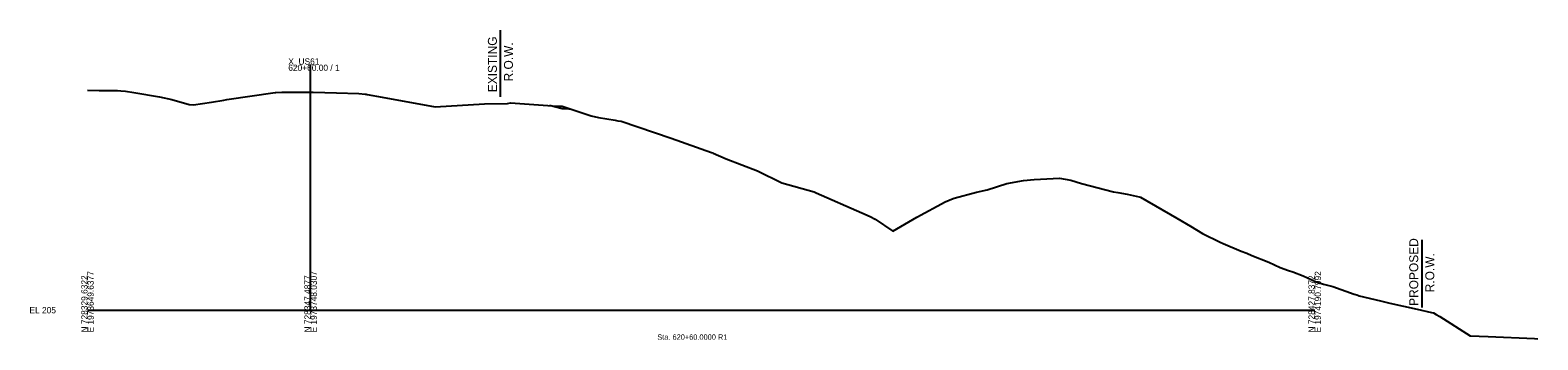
# Model space of a CAD drawing. Extents: x -26 to 1629, y -25 to 9635.
# Drawn here: x -26 to 650, y 1487 to 1625 of the extents above; entities that cross this region are included whole.
import ezdxf

# ---------------------------------------------------------------- set-up
doc = ezdxf.new("R2010")
doc.units = 0
for name, color, linetype in [('Draft_XS_Grid', 7, 'Continuous'), ('Draft_XS_Text', 7, 'Continuous'), ('DTM_X_GROUND', 7, 'Continuous'), ('XS_CELL', 7, 'Continuous'), ('XS_P_GROUND', 7, 'Continuous'), ('XS_P_ROW', 7, 'Continuous'), ('XS_X_ROW', 7, 'Continuous')]:
    doc.layers.add(name, color=color, linetype=linetype)

msp = doc.modelspace()

# ---------------------------------------------------------------- linework, layer by layer
at = {"layer": 'DTM_X_GROUND'}
msp.add_lwpolyline([(0, 1598.55), (5.26, 1598.48), (13.43, 1598.36), (14.97, 1598.25), (17.1, 1598.1), (20.71, 1597.57), (32.23, 1595.59), (37.8, 1594.33), (45.55, 1592.11), (47.57, 1592.04), (55.59, 1593.22), (61.06, 1594.14), (62.42, 1594.35), (84.15, 1597.45), (84.34, 1597.48), (84.48, 1597.49), (87.16, 1597.65), (94.94, 1597.67), (101.09, 1597.69), (111.61, 1597.33), (121.66, 1597), (124.38, 1596.78), (124.83, 1596.74), (125.4, 1596.65), (132.11, 1595.44), (155.87, 1591.1), (177.97, 1592.46), (188.31, 1592.66), (189.65, 1592.95), (208.37, 1591.53), (209.54, 1591.41), (209.82, 1591.37), (212.79, 1591.37), (220.86, 1588.66), (225.67, 1587), (229.02, 1586.29), (236.45, 1585.1), (237.63, 1584.83), (239.21, 1584.68), (261.6, 1577.1), (261.62, 1577.09), (261.62, 1577.09), (261.63, 1577.09), (279.61, 1570.66), (280.19, 1570.47), (280.36, 1570.41), (286.24, 1567.82), (300.22, 1562.41), (311.17, 1557.04), (325.62, 1552.95), (326.01, 1552.82), (326.22, 1552.74), (326.62, 1552.61), (346.99, 1543.61), (350.72, 1541.9), (353.04, 1540.83), (360.96, 1535.47), (371.74, 1541.68), (384.35, 1548.54), (387.99, 1550.02), (388.42, 1550.2), (398.49, 1552.87), (403.27, 1553.94), (411.95, 1556.79), (419.48, 1558.15), (424.27, 1558.6), (429.89, 1558.84), (435.65, 1559.08), (440.7, 1558.27), (445.44, 1556.8), (459.88, 1553.08), (461.83, 1552.67), (466.01, 1552.02), (471.31, 1550.77), (471.89, 1550.61), (488.17, 1541.2), (494.33, 1537.57), (499.64, 1534.37), (507.6, 1530.51), (508.98, 1529.93), (517.05, 1526.42), (519.6, 1525.53), (521.76, 1524.52), (529.47, 1521.57), (534.48, 1519.05), (538.28, 1517.73), (540.16, 1517.25), (544.76, 1515.36), (550.59, 1512.76), (553.88, 1511.7), (558.1, 1510.64), (567.74, 1507.19), (568.92, 1506.81), (569.56, 1506.6), (569.92, 1506.5), (579.42, 1504.25), (583.67, 1503.09), (595.99, 1500.38), (602.36, 1499), (603.22, 1498.85), (604.49, 1498.13), (606.03, 1497.16), (619.66, 1488.54), (627.75, 1488.16), (648.45, 1487.32), (650, 1487.23)], dxfattribs=at)
at = {"layer": 'XS_CELL'}
for p, q in [((100, 1500), (100, 1610)), ((0, 1500), (100, 1500)), ((100, 1500), (550, 1500))]:
    msp.add_line(p, q, dxfattribs=at)
at = {"layer": 'XS_P_GROUND'}
msp.add_line((212.79, 1590.25), (207.09, 1591.63), dxfattribs=at)
msp.add_lwpolyline([(216.96, 1589.97), (216.84, 1589.97), (216.84, 1589.97), (215.68, 1590.05), (215.67, 1590.05), (214.53, 1590.13), (214.49, 1590.13), (213.37, 1590.21), (213.35, 1590.21), (212.79, 1590.25)], dxfattribs=at)
at = {"layer": 'XS_P_ROW'}
msp.add_line((598, 1531.55), (598, 1501.23), dxfattribs=at)
at = {"layer": 'XS_X_ROW'}
msp.add_line((185, 1625.44), (185, 1595.54), dxfattribs=at)

# ---------------------------------------------------------------- texts
at = {"layer": 'Draft_XS_Grid'}
msp.add_text('-', height=0.0001, dxfattribs=at).set_placement((0, 1500))
at = {"layer": 'Draft_XS_Text'}
msp.add_text('Sta. 620+60.0000 R1', height=2.4, dxfattribs=at).set_placement((255.37, 1486.75))
at = {"layer": 'XS_CELL'}
for s, p in [('X_US61', (90, 1610)), ('620+60.00 / 1', (90, 1607.2)), ('EL 205', (-26, 1498.6))]:
    msp.add_text(s, height=2.8, dxfattribs=at).set_placement(p)
for s, p in [('N 728329.6322', (0, 1490)), ('E 1973649.6377', (2.8, 1490)), ('N 728347.4877', (100, 1490)), ('E 1973748.0307', (102.8, 1490)), ('N 728427.8372', (550, 1490)), ('E 1974190.7992', (552.8, 1490))]:
    msp.add_text(s, height=2.8, rotation=90, dxfattribs=at).set_placement(p)
at = {"layer": 'XS_P_ROW'}
for s, p in [('PROPOSED', (596.37, 1501.93)), ('R.O.W.', (603.57, 1508.01))]:
    msp.add_text(s, height=4, rotation=90, dxfattribs=at).set_placement(p)
at = {"layer": 'XS_X_ROW'}
for s, p in [('EXISTING', (183.46, 1597.63)), ('R.O.W.', (190.66, 1602.47))]:
    msp.add_text(s, height=4, rotation=90, dxfattribs=at).set_placement(p)

doc.saveas('drawing.dxf')
